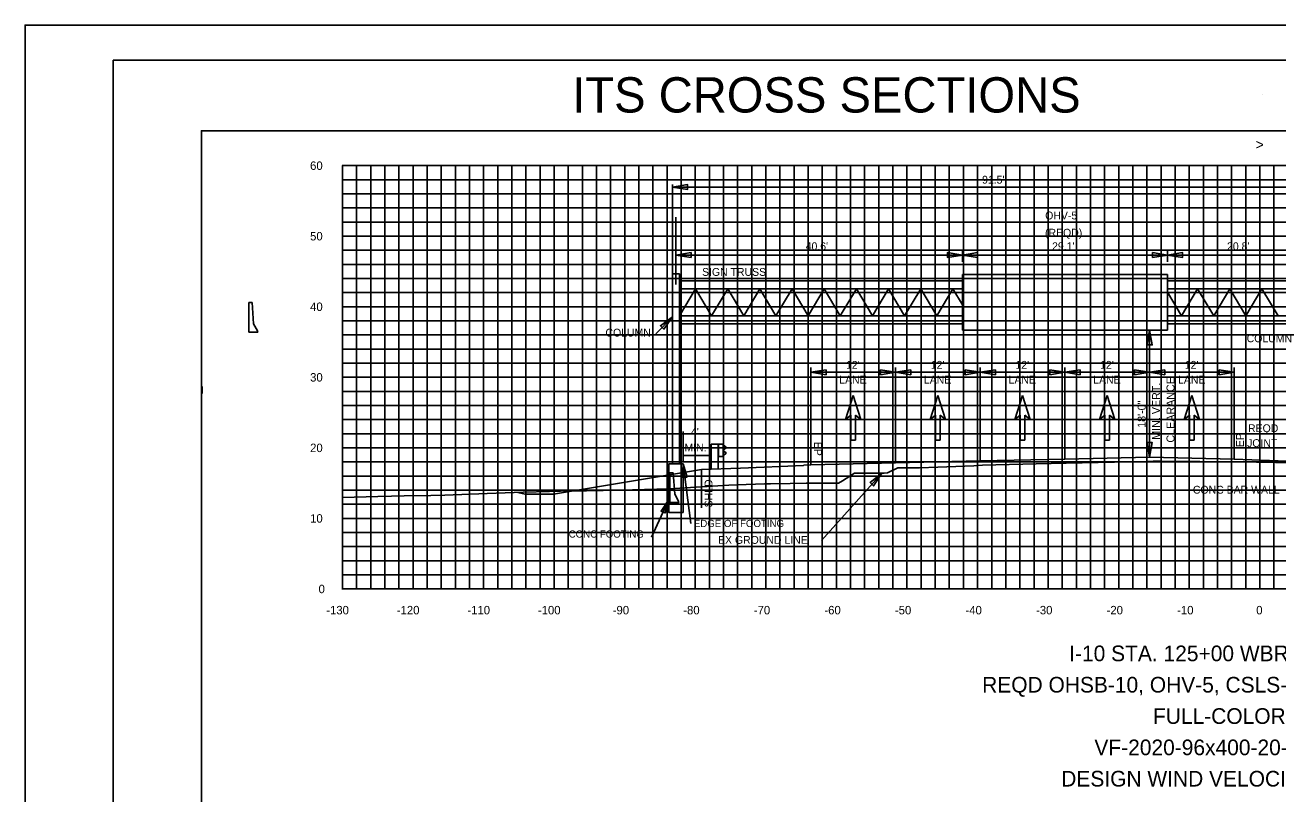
# Model space of a CAD drawing. Extents: x 2193008 to 2198143, y 1236112 to 1237864.
# Drawn here: x 2194512.7 to 2194690.3, y 1237229.1 to 1237338 of the extents above; entities that cross this region are included whole.
import ezdxf

# ---------------------------------------------------------------- set-up
doc = ezdxf.new("R2010")
doc.units = 0
for name, color, linetype in [('10', 7, 'Continuous'), ('2', 7, 'Continuous'), ('3', 7, 'Continuous'), ('31', 7, 'Continuous'), ('60', 7, 'Continuous'), ('ANNO-SHT', 7, 'Continuous'), ('AXIS', 7, 'Continuous'), ('CL-CNST', 7, 'Continuous'), ('DRAINAGE', 7, 'Continuous'), ('GSBWFILL', 7, 'Continuous'), ('GSDIMS', 7, 'Continuous'), ('Level 1', 7, 'Continuous'), ('Level 28', 7, 'Continuous'), ('Level 55', 7, 'Continuous'), ('Level 61', 7, 'Continuous'), ('Level 62', 7, 'Continuous'), ('M-ROADS', 7, 'Continuous'), ('SHT-BDR', 7, 'Continuous'), ('SHT-BNDRY', 7, 'Continuous'), ('V7Level1', 7, 'Continuous')]:
    doc.layers.add(name, color=color, linetype=linetype)

# ---------------------------------------------------------------- blocks, each defined once
blk = doc.blocks.new('SC47208')
at = {"layer": 'Level 1'}
blk.add_line((0, 0), (0, 0), dxfattribs=at)

msp = doc.modelspace()

# ---------------------------------------------------------------- linework, layer by layer
msp.add_line((2194604.95, 1237301.25), (2194604.95, 1237310.79))
at = {"layer": '2'}
msp.add_lwpolyline([(2194537.8, 1237286.82), (2194537.79, 1237285.82)], dxfattribs=at)
msp.add_lwpolyline([(2194537.8, 1237286.82), (2194537.79, 1237285.82)], dxfattribs=at)
at = {"layer": '3'}
for p, q in [((2194604.45, 1237315.42), (2194604.45, 1237302.78)), ((2194695.83, 1237315.08), (2194604.45, 1237315.08)), ((2194604.45, 1237302.78), (2194604.45, 1237275.83)), ((2194605.45, 1237302.78), (2194605.45, 1237275.83)), ((2194645.54, 1237294.78), (2194645.54, 1237302.7)), ((2194674.62, 1237294.78), (2194674.62, 1237302.7)), ((2194602.08, 1237294.25), (2194604.45, 1237296.7)), ((2194672.08, 1237276.78), (2194672.08, 1237294.78)), ((2194624.07, 1237275.72), (2194624.07, 1237289.52)), ((2194636.08, 1237275.99), (2194636.08, 1237289.5)), ((2194648.08, 1237276.25), (2194648.08, 1237289.48)), ((2194660.08, 1237276.52), (2194660.08, 1237289.48)), ((2194684.08, 1237276.52), (2194684.08, 1237289.48)), ((2194605.95, 1237276.27), (2194605.95, 1237280.42)), ((2194603.92, 1237268.97), (2194603.92, 1237275.83)), ((2194603.92, 1237275.83), (2194605.95, 1237275.83)), ((2194607.04, 1237267.4), (2194605.95, 1237275.83)), ((2194605.95, 1237268.97), (2194605.95, 1237275.83)), ((2194625.57, 1237265), (2194634.11, 1237274.52)), ((2194601.5, 1237265.46), (2194603.92, 1237270.77)), ((2194603.92, 1237268.97), (2194605.95, 1237268.97))]:
    msp.add_line(p, q, dxfattribs=at)
at = {"layer": '60'}
for p, q in [((2194557.63, 1237318.11), (2194557.69, 1237318.11)), ((2194557.69, 1237258.11), (2194557.69, 1237318.11)), ((2194557.63, 1237308.11), (2194557.69, 1237308.11)), ((2194557.63, 1237298.11), (2194557.69, 1237298.11)), ((2194557.63, 1237288.11), (2194557.69, 1237288.11)), ((2194557.63, 1237278.11), (2194557.69, 1237278.11)), ((2194557.63, 1237268.11), (2194557.69, 1237268.11)), ((2194557.63, 1237258.11), (2194557.69, 1237258.11)), ((2194557.69, 1237258.05), (2194557.69, 1237258.11)), ((2194817.69, 1237258.11), (2194557.69, 1237258.11)), ((2194577.69, 1237258.05), (2194577.69, 1237258.11)), ((2194587.69, 1237258.05), (2194587.69, 1237258.11)), ((2194597.69, 1237258.05), (2194597.69, 1237258.11)), ((2194607.69, 1237258.05), (2194607.69, 1237258.11)), ((2194617.69, 1237258.05), (2194617.69, 1237258.11)), ((2194627.69, 1237258.05), (2194627.69, 1237258.11)), ((2194637.69, 1237258.05), (2194637.69, 1237258.11)), ((2194647.69, 1237258.05), (2194647.69, 1237258.11)), ((2194657.69, 1237258.05), (2194657.69, 1237258.11)), ((2194667.69, 1237258.05), (2194667.69, 1237258.11)), ((2194677.69, 1237258.05), (2194677.69, 1237258.11)), ((2194687.69, 1237258.05), (2194687.69, 1237258.11))]:
    msp.add_line(p, q, dxfattribs=at)
at = {"layer": 'AXIS'}
msp.add_line((2194537.69, 1237243.04), (2194537.69, 1237243.05), dxfattribs=at)
at = {"layer": 'CL-CNST'}
msp.add_lwpolyline([(2194582.53, 1237271.79), (2194583.57, 1237271.53), (2194587.57, 1237271.53), (2194608.57, 1237275.03), (2194614.07, 1237275.25), (2194623, 1237275.61), (2194623.07, 1237275.68), (2194624.07, 1237275.72), (2194636.08, 1237275.99), (2194648.08, 1237276.25), (2194660.08, 1237276.52), (2194672.08, 1237276.78), (2194684.08, 1237276.52), (2194694.08, 1237276.12)], dxfattribs=at)
at = {"layer": 'GSBWFILL'}
for points in [[(2194544.89, 1237298.7), (2194544.41, 1237298.7), (2194544.41, 1237294.52), (2194545.64, 1237294.52), (2194545.66, 1237294.52), (2194545.64, 1237294.69), (2194545.09, 1237295.69), (2194544.89, 1237298.7)], [(2194604.57, 1237274.55), (2194604.09, 1237274.55), (2194604.09, 1237270.37), (2194605.32, 1237270.37), (2194605.34, 1237270.37), (2194605.32, 1237270.54), (2194604.77, 1237271.54), (2194604.57, 1237274.55)]]:
    msp.add_lwpolyline(points, dxfattribs=at)
at = {"layer": 'GSDIMS'}
for p, q in [((2194645.54, 1237305.44), (2194604.95, 1237305.44)), ((2194645.54, 1237304.46), (2194645.54, 1237306.2)), ((2194674.62, 1237305.44), (2194645.54, 1237305.44)), ((2194674.62, 1237304.46), (2194674.62, 1237306.2)), ((2194695.33, 1237305.44), (2194674.62, 1237305.44)), ((2194605.45, 1237302.78), (2194604.45, 1237302.78)), ((2194645.54, 1237301.78), (2194605.45, 1237301.78)), ((2194674.62, 1237302.7), (2194645.54, 1237302.7)), ((2194694.83, 1237301.78), (2194674.62, 1237301.78)), ((2194607.73, 1237300.67), (2194605.45, 1237296.81)), ((2194645.54, 1237300.67), (2194605.45, 1237300.67)), ((2194607.73, 1237300.67), (2194610, 1237296.81)), ((2194612.28, 1237300.67), (2194610, 1237296.81)), ((2194612.28, 1237300.67), (2194614.56, 1237296.81)), ((2194616.84, 1237300.67), (2194614.56, 1237296.81)), ((2194616.84, 1237300.67), (2194619.12, 1237296.81)), ((2194621.4, 1237300.67), (2194619.12, 1237296.81)), ((2194621.4, 1237300.67), (2194623.68, 1237296.81)), ((2194625.95, 1237300.67), (2194623.68, 1237296.81)), ((2194625.95, 1237300.67), (2194628.23, 1237296.81)), ((2194630.51, 1237300.67), (2194628.23, 1237296.81)), ((2194630.51, 1237300.67), (2194632.79, 1237296.81)), ((2194635.07, 1237300.67), (2194632.79, 1237296.81)), ((2194635.07, 1237300.67), (2194637.35, 1237296.81)), ((2194639.63, 1237300.67), (2194637.35, 1237296.81)), ((2194639.63, 1237300.67), (2194641.9, 1237296.81)), ((2194644.18, 1237300.67), (2194641.9, 1237296.81)), ((2194644.18, 1237300.67), (2194645.54, 1237298.37)), ((2194694.83, 1237300.67), (2194674.62, 1237300.67)), ((2194674.62, 1237300.17), (2194676.61, 1237296.81)), ((2194678.88, 1237300.67), (2194676.61, 1237296.81)), ((2194678.88, 1237300.67), (2194681.16, 1237296.81)), ((2194683.44, 1237300.67), (2194681.16, 1237296.81)), ((2194683.44, 1237300.67), (2194685.72, 1237296.81)), ((2194688, 1237300.67), (2194685.72, 1237296.81)), ((2194688, 1237300.67), (2194690.28, 1237296.81)), ((2194645.54, 1237296.81), (2194605.45, 1237296.81)), ((2194694.83, 1237296.81), (2194674.62, 1237296.81)), ((2194645.54, 1237295.7), (2194605.45, 1237295.7)), ((2194674.62, 1237294.78), (2194645.54, 1237294.78)), ((2194694.83, 1237295.7), (2194674.62, 1237295.7)), ((2194636.08, 1237288.82), (2194624.07, 1237288.82)), ((2194648.08, 1237288.82), (2194636.08, 1237288.82)), ((2194660.08, 1237288.82), (2194648.08, 1237288.82)), ((2194672.08, 1237288.82), (2194660.08, 1237288.82)), ((2194684.08, 1237288.82), (2194672.08, 1237288.82)), ((2194608.57, 1237269.62), (2194608.57, 1237275.03))]:
    msp.add_line(p, q, dxfattribs=at)
for points in [[(2194604.45, 1237315.08), (2194606.58, 1237314.73), (2194606.58, 1237315.42)], [(2194604.95, 1237305.44), (2194607.08, 1237305.1), (2194607.08, 1237305.79)], [(2194645.54, 1237305.44), (2194643.41, 1237305.1), (2194643.41, 1237305.79)], [(2194645.54, 1237305.44), (2194647.67, 1237305.1), (2194647.67, 1237305.79)], [(2194674.62, 1237305.44), (2194672.49, 1237305.1), (2194672.49, 1237305.79)], [(2194674.62, 1237305.44), (2194676.75, 1237305.1), (2194676.75, 1237305.79)], [(2194604.45, 1237296.7), (2194602.73, 1237295.42), (2194603.24, 1237294.95)], [(2194672.08, 1237294.78), (2194671.73, 1237292.7), (2194672.44, 1237292.7)], [(2194624.08, 1237288.82), (2194626.21, 1237288.48), (2194626.21, 1237289.17)], [(2194636.08, 1237288.82), (2194633.95, 1237288.48), (2194633.95, 1237289.17)], [(2194636.08, 1237288.82), (2194638.21, 1237288.48), (2194638.21, 1237289.17)], [(2194648.08, 1237288.82), (2194645.95, 1237288.48), (2194645.95, 1237289.17)], [(2194648.08, 1237288.82), (2194650.21, 1237288.48), (2194650.21, 1237289.17)], [(2194660.08, 1237288.82), (2194657.95, 1237288.48), (2194657.95, 1237289.17)], [(2194660.08, 1237288.82), (2194662.21, 1237288.48), (2194662.21, 1237289.17)], [(2194672.08, 1237288.82), (2194669.95, 1237288.48), (2194669.95, 1237289.17)], [(2194672.08, 1237288.82), (2194674.21, 1237288.48), (2194674.21, 1237289.17)], [(2194684.08, 1237288.82), (2194681.95, 1237288.48), (2194681.95, 1237289.17)], [(2194672.08, 1237276.78), (2194672.44, 1237278.86), (2194671.73, 1237278.86)], [(2194605.95, 1237275.83), (2194606.51, 1237273.96), (2194605.88, 1237273.88)], [(2194634.11, 1237274.52), (2194632.96, 1237272.71), (2194632.45, 1237273.19)], [(2194603.92, 1237270.77), (2194602.83, 1237269.15), (2194603.41, 1237268.89)]]:
    msp.add_lwpolyline(points, close=True, dxfattribs=at)
at = {"layer": 'Level 1'}
for p, q in [((2194609.94, 1237278.65), (2194609.94, 1237275.09)), ((2194609.94, 1237278.65), (2194611.69, 1237278.65)), ((2194610.94, 1237278.65), (2194610.94, 1237275.13)), ((2194610.99, 1237278.65), (2194610.99, 1237276.9)), ((2194611.64, 1237278.65), (2194611.64, 1237276.9)), ((2194611.69, 1237278.65), (2194611.69, 1237276.9)), ((2194611.69, 1237278.5), (2194612.06, 1237278.2)), ((2194612.06, 1237278.13), (2194611.69, 1237277.85)), ((2194610.94, 1237276.9), (2194611.69, 1237276.9)), ((2194611.69, 1237277.71), (2194612.06, 1237277.41)), ((2194612.06, 1237277.34), (2194611.69, 1237277.05))]:
    msp.add_line(p, q, dxfattribs=at)
for centre in [(2194612.02, 1237278.17), (2194612.02, 1237277.38)]:
    msp.add_arc(centre, 0.05, 313.3792, 45, dxfattribs=at)
at = {"layer": 'Level 28'}
for p, q in [((2194628.99, 1237282.12), (2194630.08, 1237285.51)), ((2194630.08, 1237285.51), (2194631.17, 1237282.12)), ((2194640.99, 1237282.12), (2194642.08, 1237285.51)), ((2194642.08, 1237285.51), (2194643.17, 1237282.12)), ((2194652.99, 1237282.12), (2194654.08, 1237285.51)), ((2194654.08, 1237285.51), (2194655.17, 1237282.12)), ((2194664.99, 1237282.12), (2194666.08, 1237285.51)), ((2194666.08, 1237285.51), (2194667.17, 1237282.12)), ((2194676.99, 1237282.12), (2194678.08, 1237285.51)), ((2194678.08, 1237285.51), (2194679.17, 1237282.12)), ((2194629.75, 1237282.76), (2194628.99, 1237282.12)), ((2194629.75, 1237279.18), (2194629.75, 1237282.76)), ((2194631.17, 1237282.12), (2194630.4, 1237282.76)), ((2194630.4, 1237282.76), (2194630.4, 1237279.18)), ((2194641.75, 1237282.76), (2194640.99, 1237282.12)), ((2194641.75, 1237279.18), (2194641.75, 1237282.76)), ((2194643.17, 1237282.12), (2194642.4, 1237282.76)), ((2194642.4, 1237282.76), (2194642.4, 1237279.18)), ((2194653.75, 1237282.76), (2194652.99, 1237282.12)), ((2194653.75, 1237279.18), (2194653.75, 1237282.76)), ((2194655.17, 1237282.12), (2194654.4, 1237282.76)), ((2194654.4, 1237282.76), (2194654.4, 1237279.18)), ((2194665.75, 1237282.76), (2194664.99, 1237282.12)), ((2194665.75, 1237279.18), (2194665.75, 1237282.76)), ((2194667.17, 1237282.12), (2194666.41, 1237282.76)), ((2194666.41, 1237282.76), (2194666.41, 1237279.18)), ((2194677.75, 1237282.76), (2194676.99, 1237282.12)), ((2194677.75, 1237279.18), (2194677.75, 1237282.76)), ((2194679.17, 1237282.12), (2194678.41, 1237282.76)), ((2194678.41, 1237282.76), (2194678.41, 1237279.18)), ((2194630.4, 1237279.18), (2194629.75, 1237279.18)), ((2194642.4, 1237279.18), (2194641.75, 1237279.18)), ((2194654.4, 1237279.18), (2194653.75, 1237279.18)), ((2194666.41, 1237279.18), (2194665.75, 1237279.18)), ((2194678.41, 1237279.18), (2194677.75, 1237279.18))]:
    msp.add_line(p, q, dxfattribs=at)
at = {"layer": 'Level 61'}
msp.add_line((2194609.94, 1237277.02), (2194605.95, 1237277.02), dxfattribs=at)
at = {"layer": 'Level 62'}
for p, q in [((2194817.69, 1237318.11), (2194557.69, 1237318.11)), ((2194559.69, 1237258.11), (2194559.69, 1237318.11)), ((2194561.69, 1237258.11), (2194561.69, 1237318.11)), ((2194563.69, 1237258.11), (2194563.69, 1237318.11)), ((2194565.69, 1237258.11), (2194565.69, 1237318.11)), ((2194567.69, 1237258.11), (2194567.69, 1237318.11)), ((2194569.69, 1237258.11), (2194569.69, 1237318.11)), ((2194571.69, 1237258.11), (2194571.69, 1237318.11)), ((2194573.69, 1237258.11), (2194573.69, 1237318.11)), ((2194575.69, 1237258.11), (2194575.69, 1237318.11)), ((2194577.69, 1237258.11), (2194577.69, 1237318.11)), ((2194577.69, 1237258.11), (2194577.69, 1237318.11)), ((2194579.69, 1237258.11), (2194579.69, 1237318.11)), ((2194581.69, 1237258.11), (2194581.69, 1237318.11)), ((2194583.69, 1237258.11), (2194583.69, 1237318.11)), ((2194585.69, 1237258.11), (2194585.69, 1237318.11)), ((2194587.69, 1237258.11), (2194587.69, 1237318.11)), ((2194589.69, 1237258.11), (2194589.69, 1237318.11)), ((2194591.69, 1237258.11), (2194591.69, 1237318.11)), ((2194593.69, 1237258.11), (2194593.69, 1237318.11)), ((2194595.69, 1237258.11), (2194595.69, 1237318.11)), ((2194597.69, 1237258.11), (2194597.69, 1237318.11)), ((2194599.69, 1237258.11), (2194599.69, 1237318.11)), ((2194601.69, 1237258.11), (2194601.69, 1237318.11)), ((2194603.69, 1237258.11), (2194603.69, 1237318.11)), ((2194605.69, 1237258.11), (2194605.69, 1237318.11)), ((2194607.69, 1237258.11), (2194607.69, 1237318.11)), ((2194609.69, 1237258.11), (2194609.69, 1237318.11)), ((2194611.69, 1237258.11), (2194611.69, 1237318.11)), ((2194613.69, 1237258.11), (2194613.69, 1237318.11)), ((2194615.69, 1237258.11), (2194615.69, 1237318.11)), ((2194617.69, 1237258.11), (2194617.69, 1237318.11)), ((2194619.69, 1237258.11), (2194619.69, 1237318.11)), ((2194621.69, 1237258.11), (2194621.69, 1237318.11)), ((2194623.69, 1237258.11), (2194623.69, 1237318.11)), ((2194625.69, 1237258.11), (2194625.69, 1237318.11)), ((2194627.69, 1237258.11), (2194627.69, 1237318.11)), ((2194629.69, 1237258.11), (2194629.69, 1237318.11)), ((2194631.69, 1237258.11), (2194631.69, 1237318.11)), ((2194633.69, 1237258.11), (2194633.69, 1237318.11)), ((2194635.69, 1237258.11), (2194635.69, 1237318.11)), ((2194637.69, 1237258.11), (2194637.69, 1237318.11)), ((2194639.69, 1237258.11), (2194639.69, 1237318.11)), ((2194641.69, 1237258.11), (2194641.69, 1237318.11)), ((2194643.69, 1237258.11), (2194643.69, 1237318.11)), ((2194645.69, 1237258.11), (2194645.69, 1237318.11)), ((2194647.69, 1237258.11), (2194647.69, 1237318.11)), ((2194649.69, 1237258.11), (2194649.69, 1237318.11)), ((2194651.69, 1237258.11), (2194651.69, 1237318.11)), ((2194653.69, 1237258.11), (2194653.69, 1237318.11)), ((2194655.69, 1237258.11), (2194655.69, 1237318.11)), ((2194657.69, 1237258.11), (2194657.69, 1237318.11)), ((2194659.69, 1237258.11), (2194659.69, 1237318.11)), ((2194661.69, 1237258.11), (2194661.69, 1237318.11)), ((2194663.69, 1237258.11), (2194663.69, 1237318.11)), ((2194665.69, 1237258.11), (2194665.69, 1237318.11)), ((2194667.69, 1237258.11), (2194667.69, 1237318.11)), ((2194669.69, 1237258.11), (2194669.69, 1237318.11)), ((2194671.69, 1237258.11), (2194671.69, 1237318.11)), ((2194673.69, 1237258.11), (2194673.69, 1237318.11)), ((2194675.69, 1237258.11), (2194675.69, 1237318.11)), ((2194677.69, 1237258.11), (2194677.69, 1237318.11)), ((2194679.69, 1237258.11), (2194679.69, 1237318.11)), ((2194681.69, 1237258.11), (2194681.69, 1237318.11)), ((2194683.69, 1237258.11), (2194683.69, 1237318.11)), ((2194685.69, 1237258.11), (2194685.69, 1237318.11)), ((2194687.69, 1237258.11), (2194687.69, 1237318.11)), ((2194689.69, 1237258.11), (2194689.69, 1237318.11)), ((2194817.69, 1237316.11), (2194557.69, 1237316.11)), ((2194817.69, 1237314.11), (2194557.69, 1237314.11)), ((2194817.69, 1237312.11), (2194557.69, 1237312.11)), ((2194817.69, 1237310.11), (2194557.69, 1237310.11)), ((2194817.69, 1237308.11), (2194557.69, 1237308.11)), ((2194817.69, 1237306.11), (2194557.69, 1237306.11)), ((2194817.69, 1237304.11), (2194557.69, 1237304.11)), ((2194817.69, 1237302.11), (2194557.69, 1237302.11)), ((2194817.69, 1237300.11), (2194557.69, 1237300.11)), ((2194817.69, 1237298.11), (2194557.69, 1237298.11)), ((2194817.69, 1237296.11), (2194557.69, 1237296.11)), ((2194817.69, 1237294.11), (2194557.69, 1237294.11)), ((2194817.69, 1237292.11), (2194557.69, 1237292.11)), ((2194817.69, 1237290.11), (2194557.69, 1237290.11)), ((2194817.69, 1237288.11), (2194557.69, 1237288.11)), ((2194817.69, 1237286.11), (2194557.69, 1237286.11)), ((2194817.69, 1237284.11), (2194557.69, 1237284.11)), ((2194817.69, 1237282.11), (2194557.69, 1237282.11)), ((2194817.69, 1237280.11), (2194557.69, 1237280.11)), ((2194817.69, 1237278.11), (2194557.69, 1237278.11)), ((2194817.69, 1237276.11), (2194557.69, 1237276.11)), ((2194817.69, 1237274.11), (2194557.69, 1237274.11)), ((2194817.69, 1237272.11), (2194557.69, 1237272.11)), ((2194817.69, 1237270.11), (2194557.69, 1237270.11)), ((2194817.69, 1237268.11), (2194557.69, 1237268.11)), ((2194817.69, 1237266.11), (2194557.69, 1237266.11)), ((2194817.69, 1237264.11), (2194557.69, 1237264.11)), ((2194817.69, 1237262.11), (2194557.69, 1237262.11)), ((2194817.69, 1237260.11), (2194557.69, 1237260.11)), ((2194817.69, 1237258.11), (2194557.69, 1237258.11))]:
    msp.add_line(p, q, dxfattribs=at)
msp.add_lwpolyline([(2194512.69, 1237118.04), (2194852.69, 1237118.04), (2194852.69, 1237338.04), (2194512.69, 1237338.04)], close=True, dxfattribs=at)
at = {"layer": 'M-ROADS'}
msp.add_lwpolyline([(2194557.69, 1237271.06), (2194562.71, 1237271.24), (2194564.61, 1237271.26), (2194566.43, 1237271.32), (2194570.19, 1237271.38), (2194572.21, 1237271.41), (2194578.17, 1237271.64), (2194583.3, 1237271.82), (2194587.02, 1237271.92), (2194588.59, 1237271.96), (2194590.16, 1237272.04), (2194590.69, 1237272.04), (2194592.26, 1237272.03), (2194597.03, 1237272.13), (2194603.94, 1237272.32), (2194612.46, 1237272.82), (2194613.61, 1237272.86), (2194617.48, 1237273.01), (2194617.87, 1237273.01), (2194618.35, 1237273.01), (2194621.12, 1237273.07), (2194623.42, 1237273.11), (2194625.69, 1237273.11), (2194625.91, 1237273.11), (2194627.99, 1237273.11), (2194628.55, 1237273.46), (2194630.26, 1237274.52), (2194632.15, 1237274.52), (2194634.45, 1237274.52), (2194634.94, 1237274.56), (2194636.39, 1237275.27), (2194636.94, 1237275.27), (2194639.44, 1237275.26), (2194642.08, 1237275.37), (2194647.14, 1237275.58), (2194647.72, 1237275.62), (2194648.38, 1237275.66), (2194656.02, 1237275.84), (2194660.24, 1237275.94), (2194671.63, 1237276.2), (2194672.57, 1237276.23), (2194673.79, 1237276.22), (2194684.58, 1237276.15), (2194695.23, 1237275.93)], dxfattribs=at)
at = {"layer": 'SHT-BDR'}
msp.add_lwpolyline([(2194537.69, 1237133.05), (2194837.69, 1237133.05), (2194837.69, 1237323.05), (2194537.69, 1237323.05)], close=True, dxfattribs=at)
at = {"layer": 'SHT-BNDRY'}
msp.add_lwpolyline([(2194525.19, 1237123.04), (2194847.69, 1237123.04), (2194847.69, 1237333.04), (2194525.19, 1237333.04)], close=True, dxfattribs=at)
at = {"layer": 'V7Level1'}
msp.add_lwpolyline([(2194605.95, 1237268.97), (2194603.92, 1237268.97), (2194603.92, 1237275.83), (2194605.95, 1237275.83)], close=True, dxfattribs=at)

# ---------------------------------------------------------------- block references
at = {"layer": 'DRAINAGE', "xscale": 0.20000000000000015, "yscale": 0.20000000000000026, "rotation": -116.41666666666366}
msp.add_blockref('SC47208', (2194688.01, 1237328.23), dxfattribs=at)
msp.add_blockref('SC47208', (2194688.01, 1237328.23), dxfattribs=at)

# ---------------------------------------------------------------- texts
at = {"layer": '10'}
for s, p in [('-130', (2194555.38, 1237254.51)), ('-120', (2194565.38, 1237254.51))]:
    msp.add_text(s, height=1.2, rotation=360, dxfattribs=at).set_placement(p)
for s, p in [('-110', (2194575.38, 1237254.51)), ('-100', (2194585.38, 1237254.51)), ('-90', (2194595.98, 1237254.51)), ('-80', (2194605.98, 1237254.51)), ('-70', (2194615.98, 1237254.51)), ('-60', (2194625.98, 1237254.51)), ('-50', (2194635.98, 1237254.51)), ('-40', (2194645.98, 1237254.51)), ('-30', (2194655.98, 1237254.51)), ('-20', (2194665.98, 1237254.51)), ('-10', (2194675.98, 1237254.51)), ('0', (2194687.19, 1237254.51))]:
    msp.add_text(s, height=1.2, dxfattribs=at).set_placement(p)
at = {"layer": '31'}
for s, p in [('60', (2194553.09, 1237317.51)), ('50', (2194553.09, 1237307.51)), ('40', (2194553.09, 1237297.51)), ('30', (2194553.09, 1237287.51)), ('20', (2194553.09, 1237277.51)), ('10', (2194553.09, 1237267.51)), ('0', (2194554.29, 1237257.51))]:
    msp.add_text(s, height=1.2, dxfattribs=at).set_placement(p)
at = {"layer": '60'}
msp.add_text('>', height=1.5, dxfattribs=at).set_placement((2194687.08, 1237320.36))
at = {"layer": 'ANNO-SHT'}
msp.add_text('              ITS CROSS SECTIONS               ', height=4.9995, rotation=360, dxfattribs=at).set_placement((2194564.23, 1237325.64))
at = {"layer": 'Level 55'}
for s, height, p in [("91.5'", 1.11, (2194648.33, 1237315.56)), ("40.6'", 1.11, (2194623.33, 1237306.13)), ("29.1'", 1.11, (2194658.25, 1237306.13)), ("20.8'", 1.11, (2194683.05, 1237306.13)), ('I-10 STA. 125+00 WBR & EBR', 2.2209, (2194660.68, 1237247.87)), ('REQD OHSB-10, OHV-5, CSLS-6, & CSLS-7', 2.2209, (2194648.34, 1237243.43)), ('FULL-COLOR DMS', 2.2209, (2194672.55, 1237238.99)), ('VF-2020-96x400-20-RGB', 2.2209, (2194664.25, 1237234.55)), ('DESIGN WIND VELOCITY 100 MPH', 2.2209, (2194659.55, 1237230.11))]:
    msp.add_text(s, height=height, dxfattribs=at).set_placement(p)
for s, height, rotation, p in [('OHV-5', 1.11, 360, (2194657.28, 1237310.49)), ('(REQD)', 1.11, 360, (2194657.25, 1237308.05)), ('SIGN TRUSS', 1.11, 360, (2194608.64, 1237302.49)), ('COLUMN', 1.11, 360, (2194594.95, 1237293.89)), ('COLUMN', 1.11, 360, (2194685.83, 1237293.08)), ("12'", 1.11, 360, (2194629.05, 1237289.32)), ("12'", 1.11, 360, (2194641.06, 1237289.32)), ("12'", 1.11, 360, (2194653.06, 1237289.32)), ("12'", 1.11, 360, (2194665.06, 1237289.32)), ("12'", 1.11, 360, (2194677.06, 1237289.32)), ('LANE', 1.11, 360, (2194628.09, 1237287.21)), ('LANE', 1.11, 360, (2194640.09, 1237287.21)), ('LANE', 1.11, 360, (2194652.09, 1237287.21)), ('LANE', 1.11, 360, (2194664.09, 1237287.21)), ('MIN. VERT.', 1.135, 90, (2194673.56, 1237279.26)), ('CLEARANCE', 1.135, 90, (2194675.61, 1237278.86)), ('LANE', 1.11, 360, (2194676.1, 1237287.21)), ('18\'-0"', 1.135, 90, (2194671.52, 1237280.95)), ("4'", 1.11, 360, (2194607.07, 1237279.83)), ('EP', 1.11, 90, (2194685.43, 1237278.22)), ('REQD', 1.11, 360, (2194686.03, 1237280.34)), ('MIN.', 1.11, 360, (2194606.15, 1237277.61)), ('EP', 1.11, 270, (2194624.53, 1237278.96)), ('JOINT', 1.11, 360, (2194685.89, 1237278.23)), ('SHLD', 1.11, 90, (2194610.11, 1237269.68)), ('CONC BAR WALL', 1.1105, 360, (2194678.21, 1237271.62)), ('EDGE OF FOOTING', 1.0246, 360, (2194607.48, 1237266.89)), ('CONC FOOTING', 1.0246, 360, (2194589.74, 1237265.39)), ('EX GROUND LINE', 1.1105, 360, (2194610.91, 1237264.51))]:
    msp.add_text(s, height=height, rotation=rotation, dxfattribs=at).set_placement(p)

doc.saveas('drawing.dxf')
